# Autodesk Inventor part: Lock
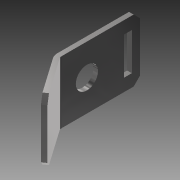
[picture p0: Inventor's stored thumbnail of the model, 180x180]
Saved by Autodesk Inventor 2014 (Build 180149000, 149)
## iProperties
Created: 2009-03
Part Number: Lock
Document SubType Name: Modeling
Designer: tangg
Density: 7.84 g/cm^3
Material: Steel, High Strength Low Alloy
Mass: 9.0689 g
Surface Area: 17.998 cm^2
Volume: 1.15675 cm^3
Appearance: Steel - Polished
Author: tangg
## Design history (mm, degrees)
sketch "Sketch1"
  geometry: L1 (0, 17)-(1.5, 17); L2 (1.5, 17)-(1.5, 0); L3 (1.5, -25)-(0, -25); L4 (0, -25)-(0, 0); L5 (0, 0)-(1.5, 0); L6 (0, 0)-(0, 17); L7 (1.5, 0)-(1.5, -25); 1 further point
  constraints: 14 end point, 5 parallel, 2 perpendicular, 1 coincident, 1 horizontal
  dimensions: "d6" = 1.5 distance between parallel lines of L2 L4; "d8" = 17 distance from line of point (0, 0) L1; "d9" = 25 distance between parallel lines of L5 L3
extrude "Extrusion1" new body sketch "Sketch1" stored distance "d0" = 20; taper "d1" = 0 deg
sketch "Sketch2"
  geometry: L1 (4, 39.414)-(16, 39.414); L2 (16, 39.414)-(16, 36.914); L3 (16, 36.914)-(4, 36.914); L4 (4, 36.914)-(4, 39.414); L5 (15, 39.414)-(5, 39.414) reference; C1 r 3.568 at (10, 25); 2 further points
  constraints: 8 end point, 2 parallel, 1 centre point, 1 coincident, 1 collinear, 1 horizontal, 1 midpoint, 1 perpendicular, 1 vertical alignment
  dimensions: "d4" = 12 distance between parallel lines of L2 L4; "d5" = 2.5 distance between parallel lines of L3 L1
extrude "Extrusion2" cut sketch "Sketch2" stored distance "d2" = 20; taper "d3" = 0 deg
sketch "Sketch3"
  geometry: L1 (0, 42)-(0, 0) reference; L2 (20, 0)-(20, 42) reference; L3 (0, 17)-(20, 17); A1 r 3.568 centre (10, 25) between (6.957, 23.136) and (13.043, 23.136) reference
  constraints: 2 end point, 2 point on line, 1 perpendicular
  dimensions: "d10" = 8 distance from line of L3 A1.centre
feature "Bend Part1" sketch "Sketch3" dims "d11" = 2, "d12" = 35 deg
chamfer "Chamfer1" distance "d13" = 2; stored, may be unused: second distance "d14" = 2, angle "d15" = 45 deg
body "Solid1"
node "Reference2"
